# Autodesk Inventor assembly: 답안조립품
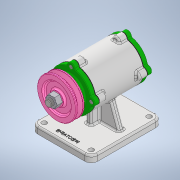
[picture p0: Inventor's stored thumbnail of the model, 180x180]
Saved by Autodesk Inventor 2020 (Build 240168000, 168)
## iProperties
Created: 2022-11
Part Number: 답안조립품
Document SubType Name: Assembly
Designer: owner
Author: owner
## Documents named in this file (12)
- C:\Users\owner\Desktop\721108V1021\답안조립품.iam
- C:\Users\owner\Desktop\721108V1021\본체.ipt
- C:\Users\owner\Desktop\721108V1021\V-벨트풀리.ipt
- C:\Users\owner\Desktop\721108V1021\개스킷.ipt
- C:\Users\owner\Desktop\721108V1021\너트 M12 x 1.25.ipt
- C:\Users\owner\Desktop\721108V1021\뒤커버.ipt
- C:\Users\owner\Desktop\721108V1021\베어링 6204.ipt
- C:\Users\owner\Desktop\721108V1021\볼트 M4 x 12.ipt
- C:\Users\owner\Desktop\721108V1021\앞커버.ipt
- C:\Users\owner\Desktop\721108V1021\오일 실.ipt
- C:\Users\owner\Desktop\721108V1021\축.ipt
- C:\Users\owner\Desktop\721108V1021\키 4 x 4.ipt
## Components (8 placed, 6 different names)
1. V-벨트풀리:1 — 각도:1
2. 개스킷:1
3. KS B 1012 클래스 1 일반 - 미터 M12x1.25:1 — 각도:1
4. KS B 2023 6204 - 20 x 47 x 14:1
5. KS B 2804 D D - 20 32 8:1
6. KS B 1311 (I) 4 x 4 x 12:1
7. KS B 2023 6204 - 20 x 47 x 14:2
8. 개스킷:2
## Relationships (1: Angle 1)
- 각도:1 [Angle]: V-벨트풀리:1 ↔ KS B 1012 클래스 1 일반 - 미터 M12x1.25:1
